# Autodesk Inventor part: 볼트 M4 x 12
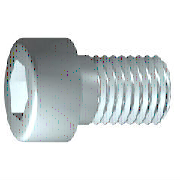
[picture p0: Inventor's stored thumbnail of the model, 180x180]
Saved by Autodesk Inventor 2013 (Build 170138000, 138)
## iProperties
IsCustomPart: 0
Created: 2012-02
Part Number: 볼트 M4 x 12
Material: 강철, 연강
Description: 6각 소켓 머리 캡 나사
Document SubType Name: Modeling
Standard: ISO 4762
Designer: mduedu
Standard Revision: Fourth edition 2004-03-01
Standards Organization: ISO
Language: ko-KR
Size Designation: M4 x 12
Categories: <MemberInstance><Categories><Category DisplayName="조임쇠" InternalName="e4da775c-781d-43d5-af7c-5136215cf5a6" Mnemonic="FSTN"><Category DisplayName="볼트" InternalN
Density: 7.86 g/cm^3
Mass: 2.23465 g
Surface Area: 3.30853 cm^2
Volume: 0.284306 cm^3
Author: mduedu
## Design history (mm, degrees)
sketch "스케치1"
  geometry: L1 (-1, 0)-(12, 0); L2 (12, 0)-(12, 2); L3 (12, 2)-(1.75, 2); L4 (1.75, 2)-(1.32, 2); L5 (1.32, 2)-(0, 2); L6 (0, 2)-(0, 3.5); L7 (0, 3.5)-(-4, 3.5); L8 (-4, 3.5)-(-4, 1.732); L9 (-4, 1.732)-(-2, 1.732); L10 (-2, 1.732)-(-1, 0); L11 (-7.2, 0)-(15.2, 0) reference; L12 (0, -0.7)-(0, 4.2) reference; L13 (1.75, 2)-(0, 2)
  constraints: 22 end point, 6 parallel, 2 collinear, 2 perpendicular, 1 horizontal, 1 point on line
  dimensions: "d1" = 10.25 distance from line of L3.end L2 (= GEL); "d2" = 0.42952 distance of L4.end L3.end (computed from GAL); "d3" = 4 distance between parallel lines of L8 L6 (= KOH); "d4" = 2 distance of L8.end L9.end (= INTI); "d5" = 60 deg angle of L10 L1; "d6" = 4 diameter of L3 L1 (= GD); "d7" = 4 diameter of L5 L1 (= BDM); "d8" = 3.4641 diameter of L9 L1 (= 1.1547 x SW); "d9" = 7 diameter of L7 L1 (= KOD); "d26" = 12 distance between parallel lines of L12 L2 (= NLG)
revolve "본체" sketch "스케치1" stored, may be unused: angle "d10" = 90 deg
sketch "스케치2"
  geometry: L1 (0, -4.9)-(0, 4.9) reference; L2 (-4.9, 0)-(4.9, 0) reference; L3 (1.732, 0)-(0.866, -1.5); L4 (0.866, -1.5)-(-0.866, -1.5); L5 (-0.866, -1.5)-(-1.732, 0); L6 (-1.732, 0)-(-0.866, 1.5); L7 (-0.866, 1.5)-(0.866, 1.5); L8 (0.866, 1.5)-(1.732, 0); 2 further points
  constraints: 12 end point, 1 coincident, 1 horizontal alignment, 1 point on line, 12 other
extrude "슬롯" join sketch "스케치2" stored distance "d11" = 10; taper "d12" = 0 deg
workplane "Work Plane1"
fillet "Fillet2" dims "d30" = 0.1 (= R)
body "Solid1"
fillet "모깎기1" dims "d17" = 0.4 (= RR)
feature "스레드" dims "d13" = 10.25 (= GEL), "d14" = 0
chamfer "모따기1" distance "d15" = 0.42941 (= -0.5 x SPD + 0.5 x GD); stored, may be unused: second distance "d16" = 0.42941 (= GUL), angle "d27" = 45 deg
other parameters: "GD" = 4 [user parameter; used in 2 equation terms], "NLG" = 12 [user parameter; used in 1 equation term], "GEL" = 10.25 [user parameter; used in 2 equation terms], "KOD" = 7 [user parameter; used in 1 equation term], "KOH" = 4 [user parameter; used in 1 equation term], "INTI" = 2 [user parameter; used in 1 equation term], "GAL" = 0.42941 (= 0.61345 x PTC) [user parameter; used in 1 equation term], "GUL" = 0.42941 (= 0.61345 x PTC) [user parameter; used in 1 equation term], "BDM" = 4 (= NND) [user parameter; used in 1 equation term], "SW" = 3 [user parameter; used in 2 equation terms], "RR" = 0.4 [user parameter; used in 1 equation term], "SPD" = 3.14117 (= NND - 1.2269 x PTC) [user parameter; used in 1 equation term], "d19" = 0, "d28" = 0, "d29" = 0, "R" = 0.1 [user parameter; used in 1 equation term], "TOA" = 30 deg [user parameter], "GD1" = 3.14117 (= THREADDIA - 1.2269 x PTC) [user parameter], "THREADDIA" = 4 [user parameter; used in 1 equation term], "FAWI" = 45 deg [user parameter], "TPU" = 14.28571 (computed from PTC) [user parameter], "PTC" = 0.7 [user parameter; used in 5 equation terms], "NND" = 4 [user parameter; used in 2 equation terms], "E0" = 3.465 (= 1.155 x SW) [user parameter]
